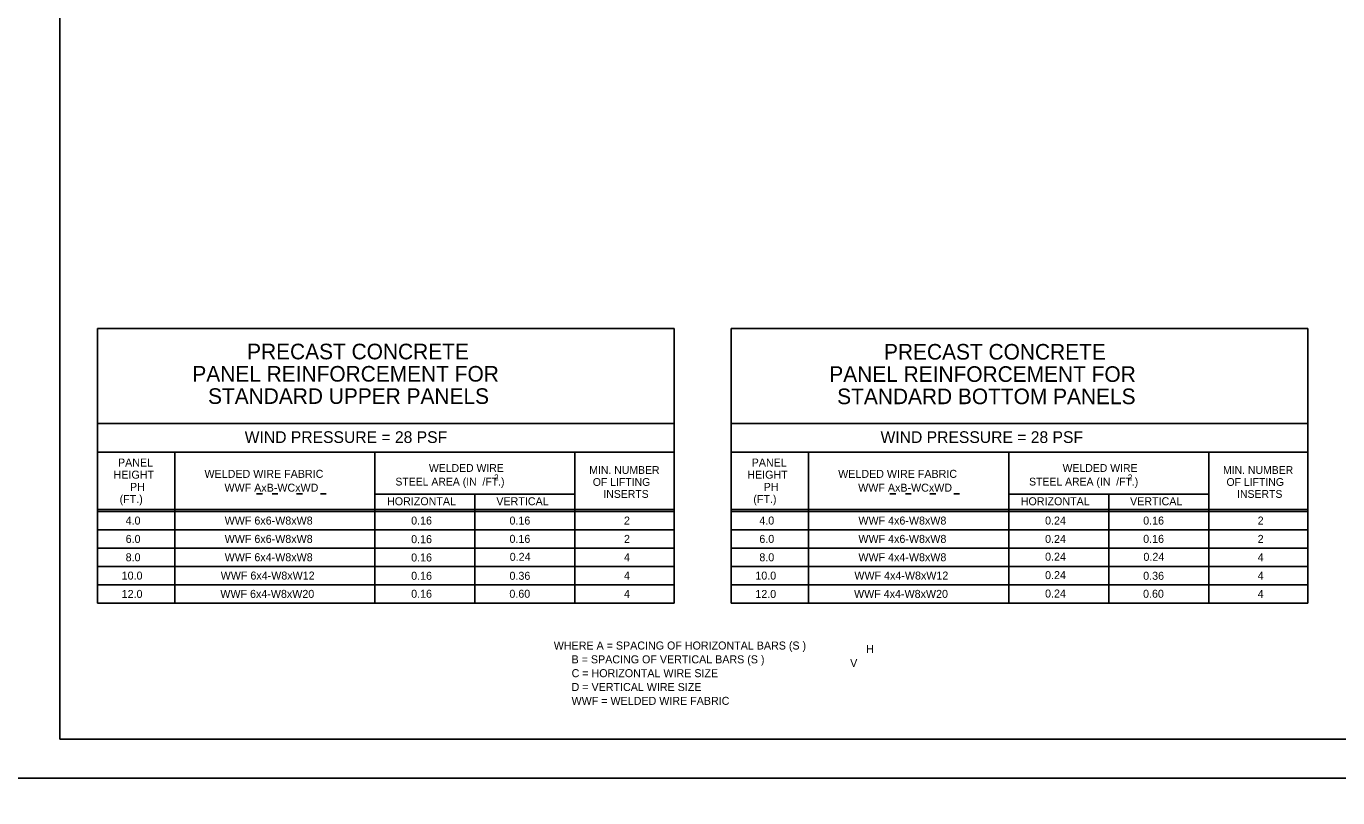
# Model space of a CAD drawing. Extents: x 3385 to 6532, y -616 to 1166.
# Drawn here: x 4629 to 5133, y -30 to 266 of the extents above; entities that cross this region are included whole.
import ezdxf

# ---------------------------------------------------------------- set-up
doc = ezdxf.new("R2010")
doc.units = 0
for name, color, linetype in [('1', 7, 'Continuous'), ('2', 7, 'Continuous'), ('PLT-BNDY', 7, 'Continuous')]:
    doc.layers.add(name, color=color, linetype=linetype)

msp = doc.modelspace()

# ---------------------------------------------------------------- linework, layer by layer
at = {"layer": '1'}
for p, q in [((4656.84, 44.97), (4656.84, 150.34)), ((4878.28, 150.34), (4656.84, 150.34)), ((4878.28, 150.34), (4878.28, 44.97)), ((4900.18, 44.97), (4900.18, 150.34)), ((5121.61, 150.34), (4900.18, 150.34)), ((5121.61, 150.34), (5121.61, 44.97)), ((4878.28, 113.92), (4656.84, 113.92)), ((5121.61, 113.92), (4900.18, 113.92)), ((4656.84, 102.94), (4878.28, 102.94)), ((4686.57, 102.94), (4686.57, 44.97)), ((4763.37, 102.94), (4763.37, 44.97)), ((4840.18, 102.94), (4840.18, 44.97)), ((4900.18, 102.94), (5121.61, 102.94)), ((4929.91, 102.94), (4929.91, 44.97)), ((5006.71, 102.94), (5006.71, 44.97)), ((5083.51, 102.94), (5083.51, 44.97)), ((4717.89, 86.89), (4720.13, 86.89)), ((4723.85, 86.89), (4726.09, 86.89)), ((4733.27, 86.89), (4735.5, 86.89)), ((4742.4, 86.89), (4744.64, 86.89)), ((4763.37, 86.81), (4840.18, 86.81)), ((4801.78, 86.81), (4801.78, 44.97)), ((4961.12, 86.89), (4963.36, 86.89)), ((4967.08, 86.89), (4969.32, 86.89)), ((4976.5, 86.89), (4978.73, 86.89)), ((4985.63, 86.89), (4987.87, 86.89)), ((5006.71, 86.81), (5083.51, 86.81)), ((5045.11, 86.81), (5045.11, 44.97)), ((4656.84, 80.92), (4878.28, 80.92)), ((4900.18, 80.92), (5121.61, 80.92)), ((4656.84, 80.17), (4878.28, 80.17)), ((4900.18, 80.17), (5121.61, 80.17)), ((4656.84, 73.13), (4878.28, 73.13)), ((4900.18, 73.13), (5121.61, 73.13)), ((4656.84, 66.09), (4878.28, 66.09)), ((4900.18, 66.09), (5121.61, 66.09)), ((4656.84, 59.05), (4878.28, 59.05)), ((4900.18, 59.05), (5121.61, 59.05)), ((4656.84, 52.01), (4878.28, 52.01)), ((4900.18, 52.01), (5121.61, 52.01)), ((4656.84, 44.97), (4878.28, 44.97)), ((4900.18, 44.97), (5121.61, 44.97))]:
    msp.add_line(p, q, dxfattribs=at)
at = {"layer": '2'}
for p, q in [((4642.34, -7.31), (4642.34, 556.69)), ((5428.34, -7.31), (4642.34, -7.31))]:
    msp.add_line(p, q, dxfattribs=at)
at = {"layer": 'PLT-BNDY'}
for points in [[(4602.34, 571.69), (5443.34, 571.69), (5443.34, -22.31), (4602.34, -22.31)], [(4602.34, -22.31), (5443.34, -22.31), (5443.34, -616.31), (4602.34, -616.31)]]:
    msp.add_lwpolyline(points, close=True, dxfattribs=at)

# ---------------------------------------------------------------- texts
at = {"layer": '1'}
for s, height, p in [('PRECAST CONCRETE', 6.0001, (4714.27, 138.56)), ('PRECAST CONCRETE', 6.0001, (4958.85, 138.46)), ('PANEL REINFORCEMENT FOR', 6.0001, (4693.25, 130)), ('PANEL REINFORCEMENT FOR', 6.0001, (4937.83, 129.9)), ('STANDARD UPPER PANELS', 6.0001, (4699.27, 121.44)), ('STANDARD BOTTOM PANELS', 6.0001, (4940.86, 121.34)), ('WIND PRESSURE = 28 PSF', 4.5001, (4713.35, 106.44)), ('WIND PRESSURE = 28 PSF', 4.5001, (4957.51, 106.44)), ('HEIGHT', 3.072, (4663.01, 92.73)), ('PANEL', 3.072, (4664.69, 97.4)), ('WELDED WIRE FABRIC', 3.072, (4697.91, 93.05)), ('WELDED WIRE', 3, (4784.09, 95.34)), ('MIN. NUMBER', 3, (4845.67, 94.56)), ('HEIGHT', 3.072, (4906.35, 92.73)), ('PANEL', 3.072, (4908.03, 97.4)), ('WELDED WIRE FABRIC', 3.072, (4941.24, 93.05)), ('WELDED WIRE', 3, (5027.43, 95.34)), ('MIN. NUMBER', 3, (5089.01, 94.56)), ('PH', 3.072, (4669.3, 88.06)), ('WWF AxB-WCxWD', 3.072, (4705.59, 87.74)), ('STEEL AREA (IN  /FT.)', 3, (4771.21, 90.1)), ('2', 2.3, (4809.16, 92.07)), ('OF LIFTING', 3, (4847.02, 89.96)), ('PH', 3.072, (4912.64, 88.06)), ('WWF AxB-WCxWD', 3.072, (4948.92, 87.74)), ('STEEL AREA (IN  /FT.)', 3, (5014.55, 90.1)), ('2', 2.3, (5052.49, 92.07)), ('OF LIFTING', 3, (5090.36, 89.96)), ('(FT.)', 3.072, (4665.32, 83.38)), ('HORIZONTAL', 3.072, (4768.01, 82.52)), ('VERTICAL', 3.072, (4809.98, 82.52)), ('INSERTS', 3, (4851.08, 85.36)), ('(FT.)', 3.072, (4908.66, 83.38)), ('HORIZONTAL', 3.072, (5011.35, 82.52)), ('VERTICAL', 3.072, (5053.32, 82.52)), ('INSERTS', 3, (5094.42, 85.36)), ('4.0', 3.072, (4667.63, 75.11)), ('WWF 6x6-W8xW8', 3.072, (4705.67, 75.11)), ('0.16', 3.072, (4777.27, 75.11)), ('0.16', 3.072, (4815.03, 75.11)), ('2', 3.07, (4858.98, 75.11)), ('4.0', 3.072, (4910.97, 75.11)), ('WWF 4x6-W8xW8', 3.072, (4949.01, 75.11)), ('0.24', 3.072, (5020.69, 75.11)), ('0.16', 3.072, (5058.37, 75.11)), ('2', 3.07, (5102.32, 75.11)), ('6.0', 3.072, (4667.64, 68.06)), ('WWF 6x6-W8xW8', 3.072, (4705.67, 68.07)), ('0.16', 3.072, (4777.27, 67.96)), ('0.16', 3.072, (4815.03, 68.08)), ('2', 3.07, (4858.99, 68.06)), ('6.0', 3.072, (4910.98, 68.06)), ('WWF 4x6-W8xW8', 3.072, (4949.01, 68.07)), ('0.24', 3.072, (5020.69, 68.04)), ('0.16', 3.072, (5058.37, 68.08)), ('2', 3.07, (5102.33, 68.06)), ('8.0', 3.072, (4667.64, 61.01)), ('WWF 6x4-W8xW8', 3.072, (4705.67, 61.03)), ('0.16', 3.072, (4777.27, 60.93)), ('0.24', 3.072, (4815.12, 61.18)), ('4', 3.07, (4858.99, 61.01)), ('8.0', 3.072, (4910.98, 61.01)), ('WWF 4x4-W8xW8', 3.072, (4949.01, 61.03)), ('0.24', 3.072, (5020.69, 61.24)), ('0.24', 3.072, (5058.46, 61.18)), ('4', 3.07, (5102.33, 61.01)), ('10.0', 3.072, (4666.11, 53.97)), ('WWF 6x4-W8xW12', 3.072, (4704.14, 53.99)), ('0.16', 3.072, (4777.27, 53.9)), ('0.36', 3.072, (4815.03, 53.9)), ('4', 3.07, (4858.99, 53.97)), ('10.0', 3.072, (4909.44, 53.97)), ('WWF 4x4-W8xW12', 3.072, (4947.47, 53.99)), ('0.24', 3.072, (5020.69, 54.16)), ('0.36', 3.072, (5058.37, 53.9)), ('4', 3.07, (5102.33, 53.97)), ('12.0', 3.072, (4666.11, 46.93)), ('WWF 6x4-W8xW20', 3.072, (4704, 46.95)), ('0.16', 3.072, (4777.27, 47)), ('0.60', 3.072, (4814.99, 47)), ('4', 3.07, (4858.99, 46.93)), ('12.0', 3.072, (4909.44, 46.93)), ('WWF 4x4-W8xW20', 3.072, (4947.34, 46.95)), ('0.24', 3.072, (5020.69, 47.09)), ('0.60', 3.072, (5058.32, 47)), ('4', 3.07, (5102.33, 46.93)), ('WHERE A = SPACING OF HORIZONTAL BARS (S )', 3.072, (4832.03, 27.12)), ('H', 3.07, (4951.94, 25.78)), ('      B = SPACING OF VERTICAL BARS (S )', 3.072, (4832.03, 21.81)), ('V', 3.07, (4945.85, 20.4)), ('      C = HORIZONTAL WIRE SIZE', 3.072, (4832.03, 16.5)), ('      D = VERTICAL WIRE SIZE', 3.072, (4832.03, 11.19)), ('      WWF = WELDED WIRE FABRIC', 3.072, (4832.03, 5.88))]:
    msp.add_text(s, height=height, dxfattribs=at).set_placement(p)

doc.saveas('drawing.dxf')
